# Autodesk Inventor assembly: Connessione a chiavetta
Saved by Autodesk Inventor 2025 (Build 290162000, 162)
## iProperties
Created: 2026-05
Part Number: Connessione a chiavetta
Document SubType Name: Assembly
Designer: Ryzen5700u
ClientObjectVersion: 1
Author: Ryzen5700u
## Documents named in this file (1)
- C:\Users\Ryzen5700u\Desktop\riduttore pompa\riduttore2\Design Accelerator\Connessione a chiavetta2.iam
